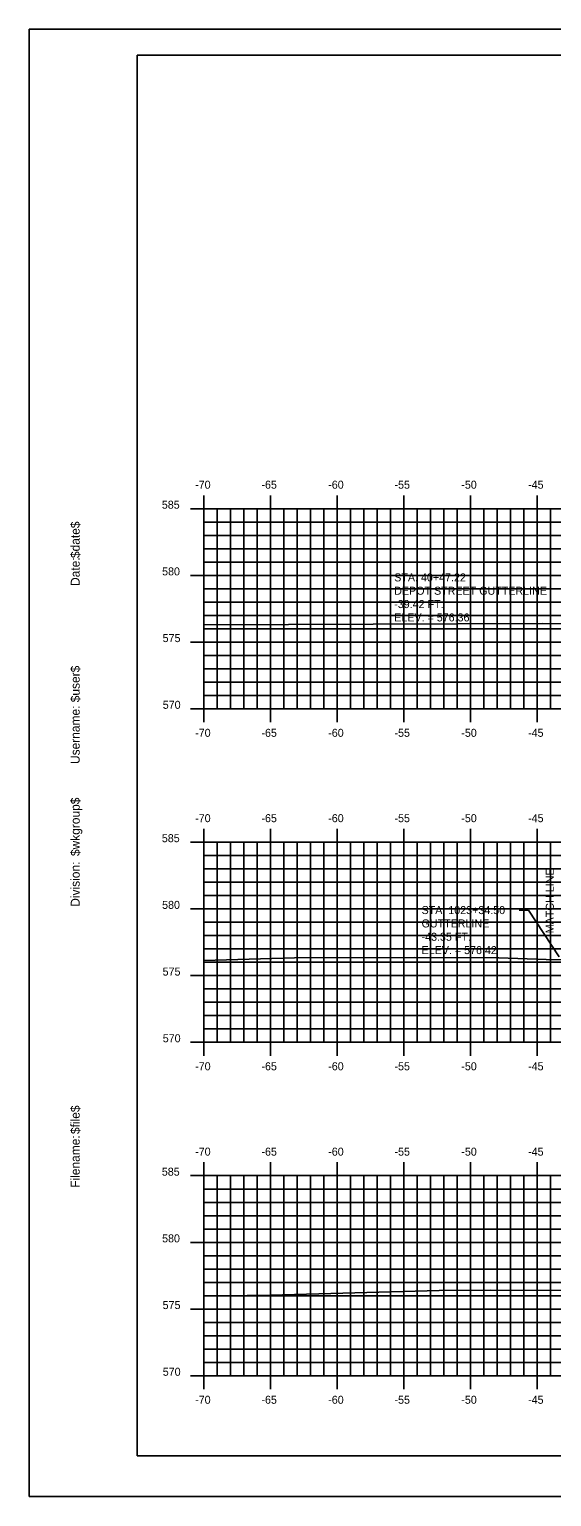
# Model space of a CAD drawing. Extents: x 1048565 to 1048735, y 781387 to 781497.
# Drawn here: x 1048564.8 to 1048604, y 781387.3 to 781497.3 of the extents above; entities that cross this region are included whole.
import ezdxf

# ---------------------------------------------------------------- set-up
doc = ezdxf.new("R2010")
doc.units = 0
for name, color, linetype in [('BORDER', 7, 'Continuous'), ('D_Text_Standard', 7, 'Continuous'), ('E_ROW_Line', 7, 'Continuous'), ('H_V ANNOTATION', 7, 'Continuous'), ('MAJOR', 7, 'Continuous'), ('MINOR', 7, 'Continuous'), ('PLOT BOUNDARY', 7, 'Continuous'), ('S_Roadway_Centerline', 7, 'Continuous')]:
    doc.layers.add(name, color=color, linetype=linetype)

msp = doc.modelspace()

# ---------------------------------------------------------------- linework, layer by layer
at = {"layer": 'BORDER'}
msp.add_lwpolyline([(1048572.88, 781390.38), (1048732.88, 781390.38), (1048732.88, 781495.38), (1048572.88, 781495.38)], close=True, dxfattribs=at)
at = {"layer": 'D_Text_Standard'}
msp.add_lwpolyline([(1048604.52, 781427.79), (1048602.21, 781431.29), (1048601.53, 781431.29)], dxfattribs=at)
at = {"layer": 'MAJOR'}
for p, q in [((1048577.88, 781462.38), (1048577.88, 781461.38)), ((1048582.88, 781462.38), (1048582.88, 781461.38)), ((1048587.88, 781462.38), (1048587.88, 781461.38)), ((1048592.88, 781462.38), (1048592.88, 781461.38)), ((1048597.88, 781462.38), (1048597.88, 781461.38)), ((1048602.88, 781462.38), (1048602.88, 781461.38)), ((1048576.87, 781461.38), (1048577.88, 781461.38)), ((1048577.88, 781461.38), (1048717.88, 781461.38)), ((1048577.88, 781446.38), (1048577.88, 781461.38)), ((1048577.88, 781446.38), (1048577.88, 781461.38)), ((1048577.88, 781461.38), (1048717.88, 781461.38)), ((1048582.88, 781446.38), (1048582.88, 781461.38)), ((1048587.88, 781446.38), (1048587.88, 781461.38)), ((1048592.88, 781446.38), (1048592.88, 781461.38)), ((1048597.88, 781446.38), (1048597.88, 781461.38)), ((1048602.88, 781446.38), (1048602.88, 781461.38)), ((1048576.87, 781456.38), (1048577.88, 781456.38)), ((1048577.88, 781456.38), (1048717.88, 781456.38)), ((1048576.87, 781451.38), (1048577.88, 781451.38)), ((1048577.88, 781451.38), (1048717.88, 781451.38)), ((1048576.87, 781446.38), (1048577.88, 781446.38)), ((1048577.88, 781446.38), (1048717.88, 781446.38)), ((1048577.88, 781446.38), (1048717.88, 781446.38)), ((1048577.88, 781445.37), (1048577.88, 781446.38)), ((1048582.88, 781445.37), (1048582.88, 781446.38)), ((1048587.88, 781445.37), (1048587.88, 781446.38)), ((1048592.88, 781445.37), (1048592.88, 781446.38)), ((1048597.88, 781445.37), (1048597.88, 781446.38)), ((1048602.88, 781445.37), (1048602.88, 781446.38)), ((1048577.88, 781437.38), (1048577.88, 781436.38)), ((1048582.88, 781437.38), (1048582.88, 781436.38)), ((1048587.88, 781437.38), (1048587.88, 781436.38)), ((1048592.88, 781437.38), (1048592.88, 781436.38)), ((1048597.88, 781437.38), (1048597.88, 781436.38)), ((1048602.88, 781437.38), (1048602.88, 781436.38)), ((1048576.87, 781436.38), (1048577.88, 781436.38)), ((1048577.88, 781436.38), (1048717.88, 781436.38)), ((1048577.88, 781421.38), (1048577.88, 781436.38)), ((1048577.88, 781421.38), (1048577.88, 781436.38)), ((1048577.88, 781436.38), (1048717.88, 781436.38)), ((1048582.88, 781421.38), (1048582.88, 781436.38)), ((1048587.88, 781421.38), (1048587.88, 781436.38)), ((1048592.88, 781421.38), (1048592.88, 781436.38)), ((1048597.88, 781421.38), (1048597.88, 781436.38)), ((1048602.88, 781421.38), (1048602.88, 781436.38)), ((1048576.87, 781431.38), (1048577.88, 781431.38)), ((1048577.88, 781431.38), (1048717.88, 781431.38)), ((1048576.87, 781426.38), (1048577.88, 781426.38)), ((1048577.88, 781426.38), (1048717.88, 781426.38)), ((1048576.87, 781421.38), (1048577.88, 781421.38)), ((1048577.88, 781421.38), (1048717.88, 781421.38)), ((1048577.88, 781421.38), (1048717.88, 781421.38)), ((1048577.88, 781420.37), (1048577.88, 781421.38)), ((1048582.88, 781420.37), (1048582.88, 781421.38)), ((1048587.88, 781420.37), (1048587.88, 781421.38)), ((1048592.88, 781420.37), (1048592.88, 781421.38)), ((1048597.88, 781420.37), (1048597.88, 781421.38)), ((1048602.88, 781420.37), (1048602.88, 781421.38)), ((1048577.88, 781412.38), (1048577.88, 781411.38)), ((1048582.88, 781412.38), (1048582.88, 781411.38)), ((1048587.88, 781412.38), (1048587.88, 781411.38)), ((1048592.88, 781412.38), (1048592.88, 781411.38)), ((1048597.88, 781412.38), (1048597.88, 781411.38)), ((1048602.88, 781412.38), (1048602.88, 781411.38)), ((1048576.87, 781411.38), (1048577.88, 781411.38)), ((1048577.88, 781411.38), (1048717.88, 781411.38)), ((1048577.88, 781396.38), (1048577.88, 781411.38)), ((1048577.88, 781396.38), (1048577.88, 781411.38)), ((1048577.88, 781411.38), (1048717.88, 781411.38)), ((1048582.88, 781396.38), (1048582.88, 781411.38)), ((1048587.88, 781396.38), (1048587.88, 781411.38)), ((1048592.88, 781396.38), (1048592.88, 781411.38)), ((1048597.88, 781396.38), (1048597.88, 781411.38)), ((1048602.88, 781396.38), (1048602.88, 781411.38)), ((1048576.87, 781406.38), (1048577.88, 781406.38)), ((1048577.88, 781406.38), (1048717.88, 781406.38)), ((1048576.87, 781401.38), (1048577.88, 781401.38)), ((1048577.88, 781401.38), (1048717.88, 781401.38)), ((1048576.87, 781396.38), (1048577.88, 781396.38)), ((1048577.88, 781396.38), (1048717.88, 781396.38)), ((1048577.88, 781396.38), (1048717.88, 781396.38)), ((1048577.88, 781395.37), (1048577.88, 781396.38)), ((1048582.88, 781395.37), (1048582.88, 781396.38)), ((1048587.88, 781395.37), (1048587.88, 781396.38)), ((1048592.88, 781395.37), (1048592.88, 781396.38)), ((1048597.88, 781395.37), (1048597.88, 781396.38)), ((1048602.88, 781395.37), (1048602.88, 781396.38))]:
    msp.add_line(p, q, dxfattribs=at)
at = {"layer": 'MINOR'}
for p, q in [((1048578.88, 781446.38), (1048578.88, 781461.38)), ((1048579.88, 781446.38), (1048579.88, 781461.38)), ((1048580.88, 781446.38), (1048580.88, 781461.38)), ((1048581.88, 781446.38), (1048581.88, 781461.38)), ((1048583.88, 781446.38), (1048583.88, 781461.38)), ((1048584.88, 781446.38), (1048584.88, 781461.38)), ((1048585.88, 781446.38), (1048585.88, 781461.38)), ((1048586.88, 781446.38), (1048586.88, 781461.38)), ((1048588.88, 781446.38), (1048588.88, 781461.38)), ((1048589.88, 781446.38), (1048589.88, 781461.38)), ((1048590.88, 781446.38), (1048590.88, 781461.38)), ((1048591.88, 781446.38), (1048591.88, 781461.38)), ((1048593.88, 781446.38), (1048593.88, 781461.38)), ((1048594.88, 781446.38), (1048594.88, 781461.38)), ((1048595.88, 781446.38), (1048595.88, 781461.38)), ((1048596.88, 781446.38), (1048596.88, 781461.38)), ((1048598.88, 781446.38), (1048598.88, 781461.38)), ((1048599.88, 781446.38), (1048599.88, 781461.38)), ((1048600.88, 781446.38), (1048600.88, 781461.38)), ((1048601.88, 781446.38), (1048601.88, 781461.38)), ((1048603.88, 781446.38), (1048603.88, 781461.38)), ((1048577.88, 781460.38), (1048717.88, 781460.38)), ((1048577.88, 781460.38), (1048578.88, 781460.38)), ((1048577.88, 781459.38), (1048717.88, 781459.38)), ((1048577.88, 781459.38), (1048578.88, 781459.38)), ((1048577.88, 781458.38), (1048717.88, 781458.38)), ((1048577.88, 781458.38), (1048578.88, 781458.38)), ((1048577.88, 781457.38), (1048717.88, 781457.38)), ((1048577.88, 781457.38), (1048578.88, 781457.38)), ((1048577.88, 781455.38), (1048717.88, 781455.38)), ((1048577.88, 781455.38), (1048578.88, 781455.38)), ((1048577.88, 781454.38), (1048717.88, 781454.38)), ((1048577.88, 781454.38), (1048578.88, 781454.38)), ((1048577.88, 781453.38), (1048717.88, 781453.38)), ((1048577.88, 781453.38), (1048578.88, 781453.38)), ((1048577.88, 781452.38), (1048717.88, 781452.38)), ((1048577.88, 781452.38), (1048578.88, 781452.38)), ((1048577.88, 781450.38), (1048717.88, 781450.38)), ((1048577.88, 781450.38), (1048578.88, 781450.38)), ((1048577.88, 781449.38), (1048717.88, 781449.38)), ((1048577.88, 781449.38), (1048578.88, 781449.38)), ((1048577.88, 781448.38), (1048717.88, 781448.38)), ((1048577.88, 781448.38), (1048578.88, 781448.38)), ((1048577.88, 781447.38), (1048717.88, 781447.38)), ((1048577.88, 781447.38), (1048578.88, 781447.38)), ((1048578.88, 781421.38), (1048578.88, 781436.38)), ((1048579.88, 781421.38), (1048579.88, 781436.38)), ((1048580.88, 781421.38), (1048580.88, 781436.38)), ((1048581.88, 781421.38), (1048581.88, 781436.38)), ((1048583.88, 781421.38), (1048583.88, 781436.38)), ((1048584.88, 781421.38), (1048584.88, 781436.38)), ((1048585.88, 781421.38), (1048585.88, 781436.38)), ((1048586.88, 781421.38), (1048586.88, 781436.38)), ((1048588.88, 781421.38), (1048588.88, 781436.38)), ((1048589.88, 781421.38), (1048589.88, 781436.38)), ((1048590.88, 781421.38), (1048590.88, 781436.38)), ((1048591.88, 781421.38), (1048591.88, 781436.38)), ((1048593.88, 781421.38), (1048593.88, 781436.38)), ((1048594.88, 781421.38), (1048594.88, 781436.38)), ((1048595.88, 781421.38), (1048595.88, 781436.38)), ((1048596.88, 781421.38), (1048596.88, 781436.38)), ((1048598.88, 781421.38), (1048598.88, 781436.38)), ((1048599.88, 781421.38), (1048599.88, 781436.38)), ((1048600.88, 781421.38), (1048600.88, 781436.38)), ((1048601.88, 781421.38), (1048601.88, 781436.38)), ((1048603.88, 781421.38), (1048603.88, 781436.38)), ((1048577.88, 781435.38), (1048717.88, 781435.38)), ((1048577.88, 781435.38), (1048578.88, 781435.38)), ((1048577.88, 781434.38), (1048717.88, 781434.38)), ((1048577.88, 781434.38), (1048578.88, 781434.38)), ((1048577.88, 781433.38), (1048717.88, 781433.38)), ((1048577.88, 781433.38), (1048578.88, 781433.38)), ((1048577.88, 781432.38), (1048717.88, 781432.38)), ((1048577.88, 781432.38), (1048578.88, 781432.38)), ((1048577.88, 781430.38), (1048717.88, 781430.38)), ((1048577.88, 781430.38), (1048578.88, 781430.38)), ((1048577.88, 781429.38), (1048717.88, 781429.38)), ((1048577.88, 781429.38), (1048578.88, 781429.38)), ((1048577.88, 781428.38), (1048717.88, 781428.38)), ((1048577.88, 781428.38), (1048578.88, 781428.38)), ((1048577.88, 781427.38), (1048717.88, 781427.38)), ((1048577.88, 781427.38), (1048578.88, 781427.38)), ((1048577.88, 781425.38), (1048717.88, 781425.38)), ((1048577.88, 781425.38), (1048578.88, 781425.38)), ((1048577.88, 781424.38), (1048717.88, 781424.38)), ((1048577.88, 781424.38), (1048578.88, 781424.38)), ((1048577.88, 781423.38), (1048717.88, 781423.38)), ((1048577.88, 781423.38), (1048578.88, 781423.38)), ((1048577.88, 781422.38), (1048717.88, 781422.38)), ((1048577.88, 781422.38), (1048578.88, 781422.38)), ((1048577.88, 781410.38), (1048717.88, 781410.38)), ((1048577.88, 781410.38), (1048578.88, 781410.38)), ((1048578.88, 781396.38), (1048578.88, 781411.38)), ((1048579.88, 781396.38), (1048579.88, 781411.38)), ((1048580.88, 781396.38), (1048580.88, 781411.38)), ((1048581.88, 781396.38), (1048581.88, 781411.38)), ((1048583.88, 781396.38), (1048583.88, 781411.38)), ((1048584.88, 781396.38), (1048584.88, 781411.38)), ((1048585.88, 781396.38), (1048585.88, 781411.38)), ((1048586.88, 781396.38), (1048586.88, 781411.38)), ((1048588.88, 781396.38), (1048588.88, 781411.38)), ((1048589.88, 781396.38), (1048589.88, 781411.38)), ((1048590.88, 781396.38), (1048590.88, 781411.38)), ((1048591.88, 781396.38), (1048591.88, 781411.38)), ((1048593.88, 781396.38), (1048593.88, 781411.38)), ((1048594.88, 781396.38), (1048594.88, 781411.38)), ((1048595.88, 781396.38), (1048595.88, 781411.38)), ((1048596.88, 781396.38), (1048596.88, 781411.38)), ((1048598.88, 781396.38), (1048598.88, 781411.38)), ((1048599.88, 781396.38), (1048599.88, 781411.38)), ((1048600.88, 781396.38), (1048600.88, 781411.38)), ((1048601.88, 781396.38), (1048601.88, 781411.38)), ((1048603.88, 781396.38), (1048603.88, 781411.38)), ((1048577.88, 781409.38), (1048717.88, 781409.38)), ((1048577.88, 781409.38), (1048578.88, 781409.38)), ((1048577.88, 781408.38), (1048717.88, 781408.38)), ((1048577.88, 781408.38), (1048578.88, 781408.38)), ((1048577.88, 781407.38), (1048717.88, 781407.38)), ((1048577.88, 781407.38), (1048578.88, 781407.38)), ((1048577.88, 781405.38), (1048717.88, 781405.38)), ((1048577.88, 781405.38), (1048578.88, 781405.38)), ((1048577.88, 781404.38), (1048717.88, 781404.38)), ((1048577.88, 781404.38), (1048578.88, 781404.38)), ((1048577.88, 781403.38), (1048717.88, 781403.38)), ((1048577.88, 781403.38), (1048578.88, 781403.38)), ((1048577.88, 781402.38), (1048717.88, 781402.38)), ((1048577.88, 781402.38), (1048578.88, 781402.38)), ((1048577.88, 781400.38), (1048717.88, 781400.38)), ((1048577.88, 781400.38), (1048578.88, 781400.38)), ((1048577.88, 781399.38), (1048717.88, 781399.38)), ((1048577.88, 781399.38), (1048578.88, 781399.38)), ((1048577.88, 781398.38), (1048717.88, 781398.38)), ((1048577.88, 781398.38), (1048578.88, 781398.38)), ((1048577.88, 781397.38), (1048717.88, 781397.38)), ((1048577.88, 781397.38), (1048578.88, 781397.38))]:
    msp.add_line(p, q, dxfattribs=at)
at = {"layer": 'PLOT BOUNDARY'}
msp.add_lwpolyline([(1048564.78, 781387.32), (1048734.78, 781387.32), (1048734.78, 781497.32), (1048564.78, 781497.32)], close=True, dxfattribs=at)
at = {"layer": 'S_Roadway_Centerline'}
for points in [[(1048577.88, 781452.67), (1048603.26, 781452.77), (1048607.31, 781452.75), (1048610.4, 781452.79), (1048624.6, 781452.9), (1048634.08, 781453.04), (1048636.82, 781453.13), (1048645.31, 781453.16), (1048645.33, 781453.16), (1048647.88, 781453.17), (1048647.95, 781453.18), (1048655.17, 781453.11), (1048661.51, 781453.07), (1048662.78, 781453.01), (1048664.6, 781452.98), (1048664.96, 781453.37), (1048665.1, 781453.53), (1048671.79, 781453.25), (1048672.03, 781453.24), (1048672.09, 781453.24), (1048672.43, 781453.23), (1048679.24, 781453.39)], [(1048577.88, 781427.52), (1048584.68, 781427.7), (1048593.66, 781427.74), (1048599.96, 781427.71), (1048599.99, 781427.71), (1048603.55, 781427.59), (1048609.6, 781427.51)], [(1048577.88, 781402.35), (1048579.14, 781402.37), (1048581.12, 781402.39), (1048581.4, 781402.4), (1048582.86, 781402.43), (1048595.51, 781402.78), (1048599.35, 781402.8), (1048610.13, 781402.74)]]:
    msp.add_lwpolyline(points, dxfattribs=at)

# ---------------------------------------------------------------- texts
at = {"layer": 'BORDER'}
for s, p in [('$date$', (1048568.56, 781457.68)), ('Date:', (1048568.56, 781455.59)), ('$user$', (1048568.56, 781446.87)), ('Username:', (1048568.56, 781442.24)), ('$wkgroup$', (1048568.56, 781435.34)), ('Division:', (1048568.56, 781431.54)), ('$file$', (1048568.56, 781414.5)), ('Filename:', (1048568.56, 781410.47))]:
    msp.add_text(s, height=0.67, rotation=90, dxfattribs=at).set_placement(p)
at = {"layer": 'D_Text_Standard'}
for s, p in [('STA. 40+47.22', (1048592.15, 781455.93)), ('DEPOT STREET GUTTERLINE', (1048592.15, 781454.93)), ('-39.42 FT.', (1048592.15, 781453.93)), ('ELEV. = 576.36', (1048592.15, 781452.93)), ('STA. 1023+34.50', (1048594.2, 781430.99)), ('GUTTERLINE', (1048594.2, 781429.99)), ('-43.35 FT.', (1048594.2, 781428.99)), ('ELEV. = 576.42', (1048594.2, 781427.99))]:
    msp.add_text(s, height=0.6, dxfattribs=at).set_placement(p)
at = {"layer": 'E_ROW_Line'}
msp.add_text('MATCH LINE', height=0.6, rotation=90, dxfattribs=at).set_placement((1048604.12, 781429.55))
at = {"layer": 'H_V ANNOTATION'}
for s, p in [('-70', (1048577.22, 781462.88)), ('-65', (1048582.19, 781462.88)), ('-60', (1048587.2, 781462.88)), ('-55', (1048592.17, 781462.88)), ('-50', (1048597.18, 781462.88)), ('-45', (1048602.19, 781462.88)), ('585', (1048574.72, 781461.38)), ('580', (1048574.74, 781456.38)), ('575', (1048574.78, 781451.38)), ('570', (1048574.79, 781446.38)), ('-70', (1048577.22, 781444.28)), ('-65', (1048582.19, 781444.28)), ('-60', (1048587.2, 781444.28)), ('-55', (1048592.17, 781444.28)), ('-50', (1048597.18, 781444.28)), ('-45', (1048602.19, 781444.28)), ('-70', (1048577.22, 781437.88)), ('-65', (1048582.19, 781437.88)), ('-60', (1048587.2, 781437.88)), ('-55', (1048592.17, 781437.88)), ('-50', (1048597.18, 781437.88)), ('-45', (1048602.19, 781437.88)), ('585', (1048574.72, 781436.38)), ('580', (1048574.74, 781431.38)), ('575', (1048574.78, 781426.38)), ('570', (1048574.79, 781421.38)), ('-70', (1048577.22, 781419.28)), ('-65', (1048582.19, 781419.28)), ('-60', (1048587.2, 781419.28)), ('-55', (1048592.17, 781419.28)), ('-50', (1048597.18, 781419.28)), ('-45', (1048602.19, 781419.28)), ('-70', (1048577.22, 781412.88)), ('-65', (1048582.19, 781412.88)), ('-60', (1048587.2, 781412.88)), ('-55', (1048592.17, 781412.88)), ('-50', (1048597.18, 781412.88)), ('-45', (1048602.19, 781412.88)), ('585', (1048574.72, 781411.38)), ('580', (1048574.74, 781406.38)), ('575', (1048574.78, 781401.38)), ('570', (1048574.79, 781396.38)), ('-70', (1048577.22, 781394.28)), ('-65', (1048582.19, 781394.28)), ('-60', (1048587.2, 781394.28)), ('-55', (1048592.17, 781394.28)), ('-50', (1048597.18, 781394.28)), ('-45', (1048602.19, 781394.28))]:
    msp.add_text(s, height=0.6, dxfattribs=at).set_placement(p)
at = {"layer": 'MAJOR'}
for p in [(1048577.87, 781446.38), (1048577.87, 781421.38), (1048577.87, 781396.38)]:
    msp.add_text('-', height=0.006, dxfattribs=at).set_placement(p)
at = {"layer": 'S_Roadway_Centerline'}
for s, p in [('C', (1048584.67, 781427.7)), ('L', (1048584.67, 781427.7)), ('L', (1048595.5, 781402.78)), ('C', (1048595.5, 781402.78))]:
    msp.add_text(s, height=0.0146, dxfattribs=at).set_placement(p)

doc.saveas('drawing.dxf')
